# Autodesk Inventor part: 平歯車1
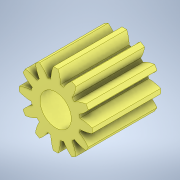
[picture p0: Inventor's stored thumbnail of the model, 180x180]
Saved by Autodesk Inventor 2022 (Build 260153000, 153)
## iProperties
CustomPartVersion: 1
Created: 2024-12
Part Number: 平歯車1
Material: Steel
Document SubType Name: Modeling
Designer: jsat7
Categories: <?xml version="1.0" encoding="UTF-16"?> <MemberInstance><Categories><FamilyTemplate><FamilyTemplateParameter ValueType="xs:double" Id="1" ObjectReferenceKey="da
Density: 1 g/cm^3
Appearance: Steel
Author: jsat7
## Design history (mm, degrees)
sketch "Sketch1"
  geometry: C1 r 3.5 at (0, 0)
  constraints: 1 centre point
  dimensions: "d0" = 7 diameter of C1 (= da_da)
extrude "Extrusion1" new body sketch "Sketch1" distance "d1" = 6.6 (= da_b); taper "d2" = 0 deg
workplane "Work Plane2"
sketch "Sketch2"
  geometry: C1 r 3.5 at (0, 0) reference; C2 r 3 at (0, 0)
  constraints: 1 centre point, 1 coincident
  dimensions: "d3" = 6 diameter of C2 (= da_d)
feature "ピッチ円直径" sketch "Sketch2" dims "d4" = 10, "d5" = 0
workplane "Work Plane8"
workplane "Work Plane9"
feature "平歯車" dims "da_b" = 6.6, "da_d" = 6, "da_aw" = 11.25, "da_da" = 7, "da_df" = 4.75, "da_dw" = 6, angle "da_beta" = 0 deg, "da_lefttooth" = 0, "da_righttooth" = 0
sketch "スケッチ3"
  geometry: C1 r 1.5 at (0, 0); 1 further point
  constraints: 1 centre point, 1 coincident
  dimensions: "d49" = 3 diameter of C1
extrude "押し出し2" cut sketch "スケッチ3" distance "d50" = 10; taper "d51" = 0 deg
body "Solid1"
body "Srf1"
other parameters: "d16" = 11.25 (= da_aw), "d17" = 0, "d34" = 15 deg (computed from da_z), "d39" = 0, "d41" = 0, "d43" = 11.25 (= da_aw), "d46" = 11.25 (= da_aw), "d47" = 0, "d48" = 0
